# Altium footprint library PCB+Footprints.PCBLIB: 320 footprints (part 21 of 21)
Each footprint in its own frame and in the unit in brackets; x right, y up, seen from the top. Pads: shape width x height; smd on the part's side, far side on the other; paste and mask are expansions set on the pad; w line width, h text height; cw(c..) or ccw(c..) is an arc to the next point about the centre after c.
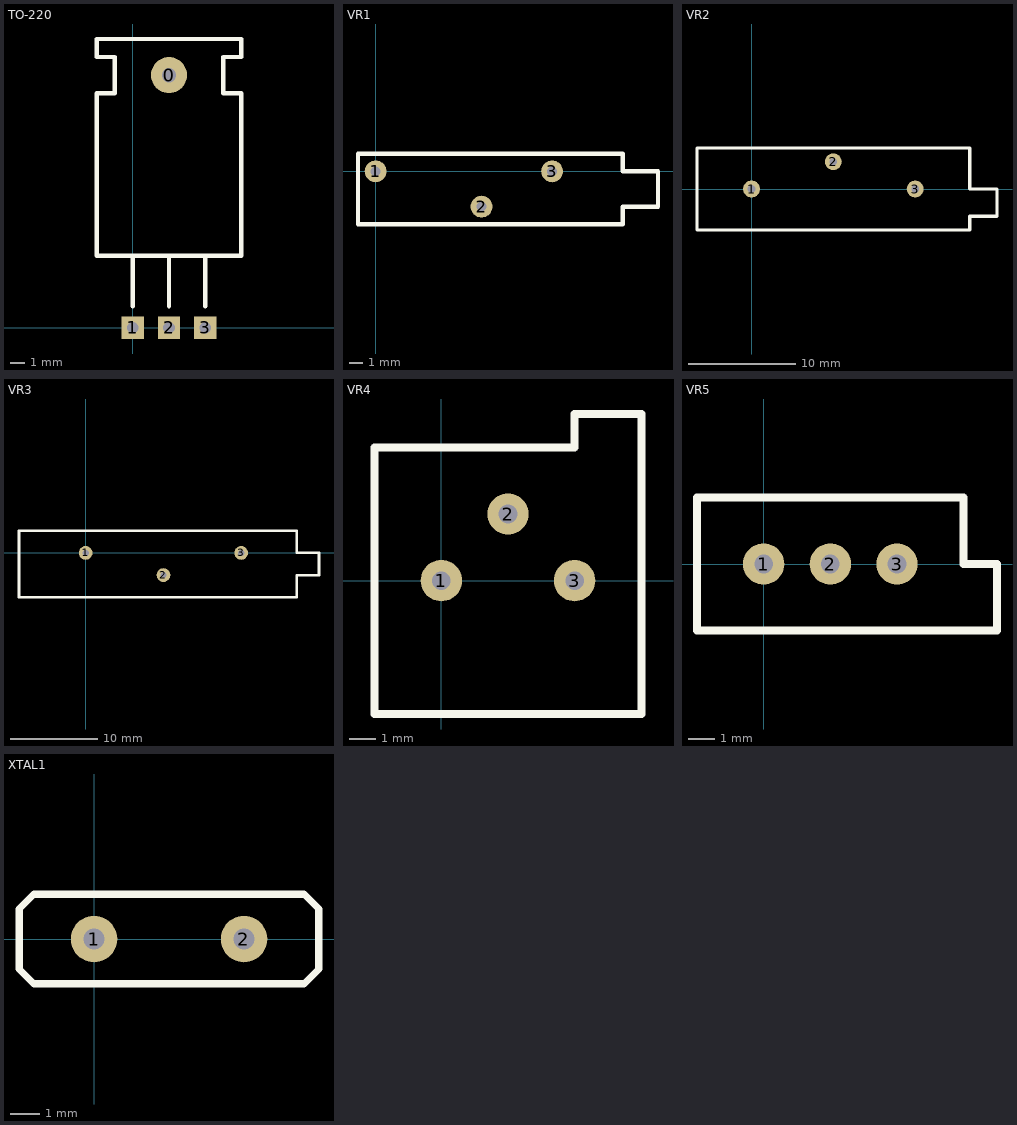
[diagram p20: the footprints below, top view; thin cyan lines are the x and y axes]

## TO-220 [mil]
pads (4):
  round 100 hole 40: 0(100,700)
  rect 62x62 hole 32: 1(0,0) 2(100,0) 3(200,0)
TopOverlay:
  lines w12: 0,60 0,200 ; 100,60 100,200 ; 200,60 200,200 ; -100,200 -100,650 -50,650 -50,750 -100,750 -100,800 300,800 300,750 250,750 250,650 300,650 300,200 -100,200

## VR1 [mil]
pads (3):
  round 62 hole 28: 1(0,0) 2(300,-100) 3(500,0)
TopOverlay:
  lines w12: -50,-150 -50,50 700,50 700,0 800,0 800,-100 700,-100 700,-150 -50,-150

## VR2 [mil]
pads (3):
  round 62 hole 28: 1(0,0) 2(300,100) 3(600,0)
TopOverlay:
  lines w12: -200,-150 800,-150 800,-100 900,-100 900,0 800,0 800,150 -200,150 -200,-150

## VR3 [mil]
pads (3):
  round 62 hole 28: 1(0,0) 2(350,-100) 3(700,0)
TopOverlay:
  lines w12: -300,-200 -300,100 950,100 950,0 1050,0 1050,-100 950,-100 950,-200 -300,-200

## VR4 [mil]
pads (3):
  round 62 hole 28: 1(0,0) 2(100,100) 3(200,0)
TopOverlay:
  lines w12: -100,-200 300,-200 300,250 200,250 200,200 -100,200 -100,-200

## VR5 [mil]
pads (3):
  round 62 hole 28: 1(0,0) 2(100,0) 3(200,0)
TopOverlay:
  lines w12: -100,-100 350,-100 350,0 300,0 300,100 -100,100 -100,-100

## XTAL1 [mil]
pads (2):
  round 62 hole 28: 1(0,0) 2(200,0)
TopOverlay:
  lines w10: -100,-40 -80,-60 280,-60 300,-40 300,40 280,60 -80,60 -100,40 -100,-40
